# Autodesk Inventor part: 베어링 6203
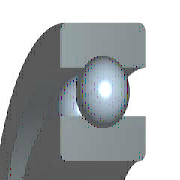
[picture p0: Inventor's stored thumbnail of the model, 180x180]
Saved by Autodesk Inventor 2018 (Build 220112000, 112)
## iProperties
IsCustomPart: 0
Created: 2018-09
Part Number: 베어링 6203
Material: 스테인리스강
Description: 깊은 그루브 볼 베어링
Document SubType Name: Modeling
Standard: KS B 2023
Standards Organization: KS
Language: ko-KR
Size Designation: 6203 - 17 x 40 x 12
Categories: <MemberInstance><Categories><Category DisplayName="샤프트 부품" InternalName="7f7aeb1f-a693-4053-b835-cee3144e0d98" Mnemonic="SHFT"><Category DisplayName="베어링" Inter
Density: 8.08 g/cm^3
Mass: 66.7997 g
Surface Area: 64.3582 cm^2
Volume: 8.26729 cm^3
Appearance: 보라색
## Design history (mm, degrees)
sketch "스케치" dims "d0" = 5.98 (= -0.26 x WD + 0.26 x BD)
  geometry: L1 (3.01, 14.25)-(8.99, 14.25); L2 (6, 14.25)-(6, 11.26); L3 (6, 14.25)-(6, 17.24); L4 (3.778, 12.249)-(0, 12.249); L5 (0, 8.5)-(12, 8.5); L6 (3.778, 16.251)-(0, 16.251); L7 (0, 20)-(12, 20); L8 (12, 8.5)-(12, 12.249); L9 (8.222, 12.249)-(12, 12.249); L10 (8.222, 16.251)-(12, 16.251); L11 (12, 20)-(12, 16.251); L12 (-1.4, 0)-(8.4, 0) reference; L13 (0, -0.3)-(0, 5.3) reference
  constraints: 22 end point, 4 point on line, 2 collinear, 2 perpendicular, 2 symmetric about line, 1 midpoint, 1 parallel, 14 other
  dimensions: "d9" = 17 diameter of L5 L12 (= WD); "d11" = 40 diameter of L7 L12 (= BD); "d12" = 12 distance between parallel lines of L8 L13 (= KB); "d13" = 24.498 diameter of L9 L12 (= 0.326 x BD + 0.674 x WD)
revolve "본체" stored, may be unused: angle "d6" = 90 deg
revolve "볼" stored, may be unused: angle "d7" = 90 deg
pattern_circular "IDS_ARRAYBALL[SIMPL:T]" dims angle "d3" = 360 deg
body "Solid1"
fillet "모깎기1" dims "d1" = 0.6 (= KRS)
other parameters: "WD" = 17 [user parameter; used in 5 equation terms], "BD" = 40 [user parameter; used in 5 equation terms], "KB" = 12 [user parameter; used in 1 equation term], "KRS" = 0.6 [user parameter; used in 1 equation term], "d4" = 0, "d5" = 0, "d8" = 0, "d14" = 0, "d15" = 0, "BBA" = 0 [user parameter], "BC0" = 4750000 [user parameter], "BC" = 9560000 [user parameter], "WR" = 8.5 (= 0.5 x WD) [user parameter]
